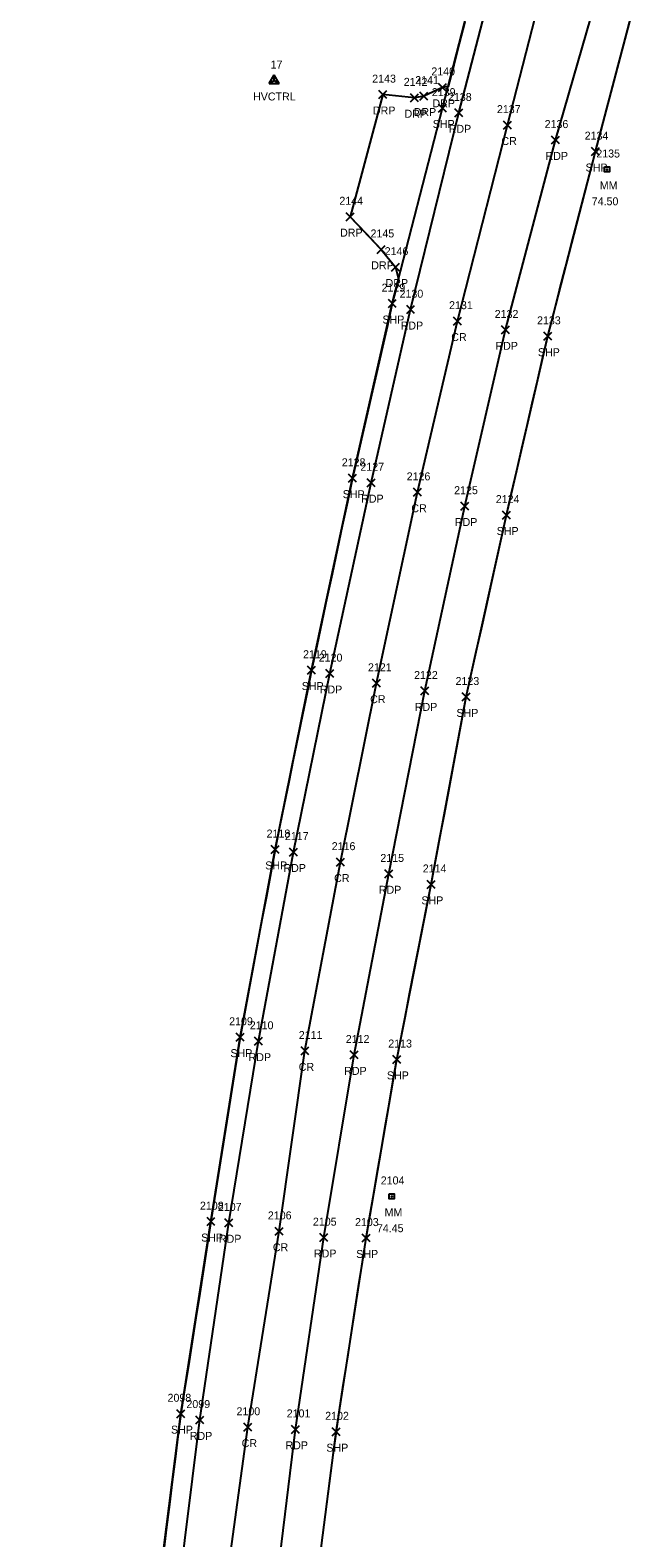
# Model space of a CAD drawing. Extents: x 1688195 to 1692013, y 424605 to 441234.
# Drawn here: x 1690667.5 to 1690820.9, y 437534.4 to 437913 of the extents above; entities that cross this region are included whole.
import ezdxf

# ---------------------------------------------------------------- set-up
doc = ezdxf.new("R2010")
doc.units = 0
for name, color, linetype in [('C_A', 7, 'Continuous'), ('C_I', 7, 'Continuous'), ('CPSM', 7, 'Continuous'), ('LSOGP', 7, 'Continuous'), ('P_A', 7, 'Continuous'), ('P_I', 7, 'Continuous'), ('P_TIC', 7, 'Continuous'), ('PET', 7, 'Continuous'), ('PRC', 7, 'Continuous'), ('PSP', 7, 'Continuous'), ('R_A', 7, 'Continuous'), ('R_I', 7, 'Continuous'), ('R_TIC', 7, 'Continuous'), ('RDP', 7, 'Continuous'), ('S_A', 7, 'Continuous'), ('S_C', 7, 'Continuous'), ('S_I', 7, 'Continuous'), ('SRM', 7, 'Continuous')]:
    doc.layers.add(name, color=color, linetype=linetype)

msp = doc.modelspace()

# ---------------------------------------------------------------- linework, layer by layer
at = {"layer": 'CPSM'}
for p, q in [((1690727.56, 437899.59), (1690728.81, 437901.75)), ((1690727.56, 437899.59), (1690728.81, 437900.31)), ((1690730.06, 437899.59), (1690728.81, 437901.75)), ((1690728.81, 437900.31), (1690728.81, 437901.75)), ((1690728.81, 437900.31), (1690728.81, 437900.31)), ((1690728.81, 437900.31), (1690730.06, 437899.59)), ((1690727.56, 437899.59), (1690730.06, 437899.59))]:
    msp.add_line(p, q, dxfattribs=at)
at = {"layer": 'LSOGP'}
for points in [[(1690776.67, 437915.01), (1690775.27, 437909.61), (1690773.88, 437904.21), (1690772.49, 437898.8), (1690771.05, 437898.6), (1690766.36, 437896.42), (1690764.05, 437895.98), (1690756.12, 437896.79), (1690747.87, 437866.12), (1690751.79, 437862.02), (1690755.7, 437857.92), (1690759.31, 437853.47), (1690760.06, 437850.44), (1690758.48, 437844.3), (1690757.23, 437838.82), (1690755.98, 437833.34), (1690754.73, 437827.86), (1690753.48, 437822.38), (1690752.23, 437816.9), (1690750.99, 437811.42), (1690749.74, 437805.94), (1690748.49, 437800.46), (1690747.2, 437794.44), (1690745.92, 437788.42), (1690744.63, 437782.39), (1690743.35, 437776.37), (1690742.06, 437770.35), (1690740.77, 437764.33), (1690739.49, 437758.3), (1690738.2, 437752.28), (1690737.06, 437746.65), (1690735.91, 437741.02), (1690734.76, 437735.4), (1690733.62, 437729.77), (1690732.47, 437724.14), (1690731.33, 437718.51), (1690730.18, 437712.88), (1690729.03, 437707.25), (1690727.94, 437701.36), (1690726.85, 437695.47), (1690725.75, 437689.58), (1690724.66, 437683.69), (1690723.57, 437677.79), (1690722.48, 437671.9), (1690721.38, 437666.01), (1690720.29, 437660.12), (1690719.37, 437654.33), (1690718.46, 437648.54), (1690717.54, 437642.75), (1690716.62, 437636.97), (1690715.7, 437631.18), (1690714.78, 437625.39), (1690713.87, 437619.61), (1690712.95, 437613.82), (1690712, 437607.79), (1690711.06, 437601.76), (1690710.11, 437595.73), (1690709.16, 437589.7), (1690708.21, 437583.67), (1690707.27, 437577.64), (1690706.32, 437571.61), (1690705.37, 437565.59), (1690704.66, 437559.89), (1690703.94, 437554.19), (1690703.22, 437548.49), (1690702.51, 437542.8), (1690701.79, 437537.1), (1690701.08, 437531.4)], [(1690740.64, 437531.86), (1690741.39, 437537.7), (1690742.14, 437543.54), (1690742.89, 437549.38), (1690743.64, 437555.22), (1690745.33, 437567.14), (1690746.26, 437573.22), (1690747.2, 437579.3), (1690748.14, 437585.38), (1690749.07, 437591.46), (1690750.01, 437597.54), (1690750.95, 437603.62), (1690751.89, 437609.7), (1690752.85, 437615.3), (1690753.81, 437620.91), (1690754.77, 437626.51), (1690755.73, 437632.11), (1690756.7, 437637.72), (1690757.66, 437643.32), (1690758.62, 437648.93), (1690759.58, 437654.53), (1690760.66, 437660.02), (1690761.75, 437665.52), (1690762.83, 437671.01), (1690763.91, 437676.5), (1690765, 437682), (1690766.08, 437687.49), (1690767.16, 437692.98), (1690768.24, 437698.48), (1690769.34, 437704.36), (1690770.44, 437710.24), (1690771.54, 437716.13), (1690772.65, 437722.01), (1690773.75, 437727.89), (1690774.85, 437733.78), (1690775.95, 437739.66), (1690777.05, 437745.54), (1690778.31, 437751.25), (1690779.57, 437756.96), (1690780.83, 437762.67), (1690782.1, 437768.38), (1690783.36, 437774.09), (1690784.62, 437779.8), (1690785.88, 437785.51), (1690787.15, 437791.22), (1690788.44, 437796.83), (1690789.73, 437802.44), (1690791.03, 437808.05), (1690792.32, 437813.66), (1690793.62, 437819.27), (1690794.91, 437824.88), (1690796.21, 437830.49), (1690797.5, 437836.1), (1690798.99, 437841.9), (1690800.49, 437847.69), (1690801.98, 437853.49), (1690803.48, 437859.29), (1690804.98, 437865.08), (1690806.47, 437870.88), (1690807.97, 437876.67), (1690809.46, 437882.47), (1690810.89, 437887.87), (1690812.31, 437893.26), (1690813.74, 437898.66), (1690815.17, 437904.06), (1690816.59, 437909.45), (1690818.02, 437914.85)]]:
    msp.add_lwpolyline(points, dxfattribs=at)
at = {"layer": 'P_TIC'}
for points in [[(1690770.1, 437892.4), (1690772.1, 437894.4)], [(1690772.1, 437892.4), (1690770.1, 437894.4)], [(1690774.14, 437891.19), (1690776.14, 437893.19)], [(1690776.14, 437891.19), (1690774.14, 437893.19)], [(1690786.43, 437888.13), (1690788.43, 437890.13)], [(1690788.43, 437888.13), (1690786.43, 437890.13)], [(1690798.47, 437884.38), (1690800.47, 437886.38)], [(1690800.47, 437884.38), (1690798.47, 437886.38)], [(1690808.46, 437881.47), (1690810.46, 437883.47)], [(1690810.46, 437881.47), (1690808.46, 437883.47)], [(1690757.48, 437843.3), (1690759.48, 437845.3)], [(1690759.48, 437843.3), (1690757.48, 437845.3)], [(1690762.08, 437841.79), (1690764.08, 437843.79)], [(1690764.08, 437841.79), (1690762.08, 437843.79)], [(1690773.84, 437838.91), (1690775.84, 437840.91)], [(1690775.84, 437838.91), (1690773.84, 437840.91)], [(1690785.88, 437836.7), (1690787.88, 437838.7)], [(1690787.88, 437836.7), (1690785.88, 437838.7)], [(1690796.5, 437835.1), (1690798.5, 437837.1)], [(1690798.5, 437835.1), (1690796.5, 437837.1)], [(1690747.49, 437799.46), (1690749.49, 437801.46)], [(1690749.49, 437799.46), (1690747.49, 437801.46)], [(1690752.16, 437798.33), (1690754.16, 437800.33)], [(1690754.16, 437798.33), (1690752.16, 437800.33)], [(1690763.83, 437795.93), (1690765.83, 437797.93)], [(1690765.83, 437795.93), (1690763.83, 437797.93)], [(1690775.69, 437792.46), (1690777.69, 437794.46)], [(1690777.69, 437792.46), (1690775.69, 437794.46)], [(1690786.15, 437790.22), (1690788.15, 437792.22)], [(1690788.15, 437790.22), (1690786.15, 437792.22)], [(1690737.2, 437751.28), (1690739.2, 437753.28)], [(1690739.2, 437751.28), (1690737.2, 437753.28)], [(1690741.78, 437750.42), (1690743.78, 437752.42)], [(1690743.78, 437750.42), (1690741.78, 437752.42)], [(1690753.49, 437747.99), (1690755.49, 437749.99)], [(1690755.49, 437747.99), (1690753.49, 437749.99)], [(1690765.63, 437746.05), (1690767.63, 437748.05)], [(1690767.63, 437746.05), (1690765.63, 437748.05)], [(1690776.05, 437744.54), (1690778.05, 437746.54)], [(1690778.05, 437744.54), (1690776.05, 437746.54)], [(1690728.03, 437706.25), (1690730.03, 437708.25)], [(1690730.03, 437706.25), (1690728.03, 437708.25)], [(1690732.64, 437705.61), (1690734.64, 437707.61)], [(1690734.64, 437705.61), (1690732.64, 437707.61)], [(1690744.44, 437703.08), (1690746.44, 437705.08)], [(1690746.44, 437703.08), (1690744.44, 437705.08)], [(1690756.6, 437700.13), (1690758.6, 437702.13)], [(1690758.6, 437700.13), (1690756.6, 437702.13)], [(1690767.24, 437697.48), (1690769.24, 437699.48)], [(1690769.24, 437697.48), (1690767.24, 437699.48)], [(1690719.29, 437659.12), (1690721.29, 437661.12)], [(1690721.29, 437659.12), (1690719.29, 437661.12)], [(1690723.9, 437658.11), (1690725.9, 437660.11)], [(1690725.9, 437658.11), (1690723.9, 437660.11)], [(1690735.55, 437655.66), (1690737.55, 437657.66)], [(1690737.55, 437655.66), (1690735.55, 437657.66)], [(1690747.91, 437654.66), (1690749.91, 437656.66)], [(1690749.91, 437654.66), (1690747.91, 437656.66)], [(1690758.58, 437653.53), (1690760.58, 437655.53)], [(1690760.58, 437653.53), (1690758.58, 437655.53)], [(1690711.95, 437612.82), (1690713.95, 437614.82)], [(1690713.95, 437612.82), (1690711.95, 437614.82)], [(1690716.45, 437612.51), (1690718.45, 437614.51)], [(1690718.45, 437612.51), (1690716.45, 437614.51)], [(1690729.06, 437610.38), (1690731.06, 437612.38)], [(1690731.06, 437610.38), (1690729.06, 437612.38)], [(1690740.31, 437608.81), (1690742.31, 437610.81)], [(1690742.31, 437608.81), (1690740.31, 437610.81)], [(1690750.89, 437608.7), (1690752.89, 437610.7)], [(1690752.89, 437608.7), (1690750.89, 437610.7)], [(1690704.37, 437564.59), (1690706.37, 437566.59)], [(1690706.37, 437564.59), (1690704.37, 437566.59)], [(1690709.13, 437563.01), (1690711.13, 437565.01)], [(1690711.13, 437563.01), (1690709.13, 437565.01)], [(1690721.22, 437561.2), (1690723.22, 437563.2)], [(1690723.22, 437561.2), (1690721.22, 437563.2)], [(1690733.16, 437560.66), (1690735.16, 437562.66)], [(1690735.16, 437560.66), (1690733.16, 437562.66)], [(1690743.39, 437560.06), (1690745.39, 437562.06)], [(1690745.39, 437560.06), (1690743.39, 437562.06)]]:
    msp.add_lwpolyline(points, dxfattribs=at)
at = {"layer": 'PET'}
for points in [[(1690672.22, 437133.51), (1690675.32, 437180.59), (1690679.01, 437229.3), (1690682.55, 437279.56), (1690686.24, 437327.7), (1690690.1, 437375.18), (1690694.44, 437424.13), (1690699.57, 437468.9), (1690704.53, 437518.9), (1690710.13, 437564.01), (1690717.45, 437613.51), (1690724.9, 437659.11), (1690733.64, 437706.61), (1690742.78, 437751.42), (1690753.16, 437799.33), (1690763.08, 437842.79), (1690775.14, 437892.19), (1690786.57, 437936.04)], [(1690696.48, 437132.39), (1690699.66, 437177.7), (1690703.13, 437226.98), (1690706.92, 437277.15), (1690710.83, 437325.78), (1690714.61, 437373.28), (1690718.51, 437419.73), (1690723.31, 437467.32), (1690728.46, 437514.97), (1690734.16, 437561.66), (1690741.31, 437609.81), (1690748.91, 437655.66), (1690757.6, 437701.13), (1690766.63, 437747.05), (1690776.69, 437793.46), (1690786.88, 437837.7), (1690799.47, 437885.38), (1690811.72, 437928.04)]]:
    msp.add_lwpolyline(points, dxfattribs=at)
at = {"layer": 'PRC'}
msp.add_lwpolyline([(1690683.84, 437132.47), (1690687.9, 437179.25), (1690690.8, 437228.34), (1690694.3, 437277.81), (1690698.39, 437326.64), (1690702.07, 437373.44), (1690706.22, 437422.68), (1690711.1, 437467.75), (1690716.15, 437518.28), (1690722.22, 437562.2), (1690730.06, 437611.38), (1690736.55, 437656.66), (1690745.44, 437704.08), (1690754.49, 437748.99), (1690764.83, 437796.93), (1690774.84, 437839.91), (1690787.43, 437889.13), (1690798.27, 437931.55)], dxfattribs=at)
at = {"layer": 'PSP'}
for points in [[(1690667.55, 437134.28), (1690670.88, 437180.54), (1690674.46, 437230.34), (1690677.75, 437279.66), (1690681.7, 437328.8), (1690685.23, 437375.51), (1690689.67, 437424.54), (1690694.03, 437469.91), (1690699.64, 437520.01), (1690705.37, 437565.59), (1690712.95, 437613.82), (1690720.29, 437660.12), (1690729.03, 437707.25), (1690738.2, 437752.28), (1690748.49, 437800.46), (1690758.48, 437844.3), (1690771.1, 437893.4), (1690782.23, 437936.63)], [(1690706.73, 437130.77), (1690709.86, 437177.48), (1690712.96, 437225.68), (1690716.45, 437277.35), (1690719.82, 437326.32), (1690723.69, 437372.72), (1690727.97, 437418.98), (1690733.02, 437466.84), (1690738.38, 437514.35), (1690744.39, 437561.06), (1690751.89, 437609.7), (1690759.58, 437654.53), (1690768.24, 437698.48), (1690777.05, 437745.54), (1690787.15, 437791.22), (1690797.5, 437836.1), (1690809.46, 437882.47), (1690820.87, 437925.64)]]:
    msp.add_lwpolyline(points, dxfattribs=at)
at = {"layer": 'R_TIC'}
for points in [[(1690755.12, 437895.79), (1690757.12, 437897.79)], [(1690757.12, 437895.79), (1690755.12, 437897.79)], [(1690763.05, 437894.98), (1690765.05, 437896.98)], [(1690765.05, 437894.98), (1690763.05, 437896.98)], [(1690765.36, 437895.42), (1690767.36, 437897.42)], [(1690767.36, 437895.42), (1690765.36, 437897.42)], [(1690770.05, 437897.6), (1690772.05, 437899.6)], [(1690772.05, 437897.6), (1690770.05, 437899.6)], [(1690746.87, 437865.12), (1690748.87, 437867.12)], [(1690748.87, 437865.12), (1690746.87, 437867.12)], [(1690754.7, 437856.92), (1690756.7, 437858.92)], [(1690756.7, 437856.92), (1690754.7, 437858.92)], [(1690758.31, 437852.47), (1690760.31, 437854.47)], [(1690760.31, 437852.47), (1690758.31, 437854.47)]]:
    msp.add_lwpolyline(points, dxfattribs=at)
at = {"layer": 'RDP'}
for points in [[(1690771.05, 437898.6), (1690766.36, 437896.42), (1690764.05, 437895.98), (1690756.12, 437896.79)], [(1690747.87, 437866.12), (1690755.7, 437857.92), (1690759.31, 437853.47)]]:
    msp.add_lwpolyline(points, dxfattribs=at)
at = {"layer": 'SRM'}
for points in [[(1690811.75, 437878.61), (1690813, 437878.61), (1690813, 437877.36), (1690811.75, 437877.36)], [(1690757.72, 437620.78), (1690758.97, 437620.78), (1690758.97, 437619.53), (1690757.72, 437619.53)]]:
    msp.add_lwpolyline(points, close=True, dxfattribs=at)
for centre in [(1690812.38, 437877.99), (1690758.35, 437620.16)]:
    msp.add_circle(centre, 0.0833, dxfattribs=at)

# ---------------------------------------------------------------- texts
at = {"layer": 'C_A'}
msp.add_text('HVCTRL', height=2, dxfattribs=at).set_placement((1690723.51, 437895.31))
at = {"layer": 'C_I'}
msp.add_text('17', height=2, dxfattribs=at).set_placement((1690727.91, 437903.31))
at = {"layer": 'P_A'}
for s, p in [('SHP', (1690768.63, 437888.4)), ('RDP', (1690772.63, 437887.19)), ('CR', (1690785.87, 437884.13)), ('RDP', (1690796.95, 437880.38)), ('SHP', (1690807, 437877.47)), ('SHP', (1690756.01, 437839.3)), ('RDP', (1690760.57, 437837.79)), ('CR', (1690773.28, 437834.91)), ('RDP', (1690784.36, 437832.7)), ('SHP', (1690795.03, 437831.1)), ('SHP', (1690746.02, 437795.46)), ('RDP', (1690750.65, 437794.33)), ('CR', (1690763.26, 437791.93)), ('RDP', (1690774.18, 437788.46)), ('SHP', (1690784.68, 437786.22)), ('SHP', (1690735.74, 437747.28)), ('RDP', (1690740.26, 437746.42)), ('CR', (1690752.92, 437743.99)), ('RDP', (1690764.12, 437742.05)), ('SHP', (1690774.58, 437740.54)), ('SHP', (1690726.57, 437702.25)), ('RDP', (1690731.13, 437701.61)), ('CR', (1690743.87, 437699.08)), ('RDP', (1690755.09, 437696.13)), ('SHP', (1690765.78, 437693.48)), ('SHP', (1690717.83, 437655.12)), ('RDP', (1690722.39, 437654.11)), ('CR', (1690734.98, 437651.66)), ('RDP', (1690746.4, 437650.66)), ('SHP', (1690757.12, 437649.53)), ('SHP', (1690710.48, 437608.82)), ('RDP', (1690714.94, 437608.51)), ('CR', (1690728.49, 437606.38)), ('RDP', (1690738.8, 437604.81)), ('SHP', (1690749.42, 437604.7)), ('SHP', (1690702.91, 437560.59)), ('RDP', (1690707.62, 437559.01)), ('CR', (1690720.65, 437557.2)), ('RDP', (1690731.65, 437556.66)), ('SHP', (1690741.92, 437556.06))]:
    msp.add_text(s, height=2, dxfattribs=at).set_placement(p)
at = {"layer": 'P_I'}
for s, p in [('2139', (1690768.4, 437896.4)), ('2138', (1690772.45, 437895.19)), ('2137', (1690784.74, 437892.13)), ('2136', (1690796.72, 437888.38)), ('2134', (1690806.77, 437885.47)), ('2129', (1690755.78, 437847.3)), ('2130', (1690760.3, 437845.79)), ('2131', (1690772.72, 437842.91)), ('2132', (1690784.18, 437840.7)), ('2133', (1690794.81, 437839.1)), ('2128', (1690745.79, 437803.46)), ('2127', (1690750.47, 437802.33)), ('2126', (1690762.08, 437799.93)), ('2125', (1690774, 437796.46)), ('2124', (1690784.45, 437794.22)), ('2119', (1690736.07, 437755.28)), ('2120', (1690740, 437754.42)), ('2121', (1690752.36, 437751.99)), ('2122', (1690763.94, 437750.05)), ('2123', (1690774.35, 437748.54)), ('2118', (1690726.91, 437710.25)), ('2117', (1690731.51, 437709.61)), ('2116', (1690743.26, 437707.08)), ('2115', (1690755.47, 437704.13)), ('2114', (1690766.12, 437701.48)), ('2109', (1690717.51, 437663.12)), ('2110', (1690722.69, 437662.11)), ('2111', (1690734.99, 437659.66)), ('2112', (1690746.79, 437658.66)), ('2113', (1690757.46, 437657.53)), ('2108', (1690710.18, 437616.82)), ('2107', (1690714.68, 437616.51)), ('2106', (1690727.23, 437614.38)), ('2105', (1690738.54, 437612.81)), ('2103', (1690749.11, 437612.7)), ('2098', (1690702.04, 437568.59)), ('2099', (1690706.78, 437567.01)), ('2100', (1690719.36, 437565.2)), ('2101', (1690731.96, 437564.66)), ('2102', (1690741.62, 437564.06))]:
    msp.add_text(s, height=2, dxfattribs=at).set_placement(p)
at = {"layer": 'R_A'}
for p in [(1690753.61, 437891.79), (1690761.54, 437890.98), (1690763.84, 437891.42), (1690768.54, 437893.6), (1690745.36, 437861.12), (1690753.19, 437852.92), (1690756.79, 437848.47)]:
    msp.add_text('DRP', height=2, dxfattribs=at).set_placement(p)
at = {"layer": 'R_I'}
for s, p in [('2140', (1690768.27, 437901.6)), ('2143', (1690753.43, 437899.79)), ('2142', (1690761.35, 437898.98)), ('2141', (1690764.23, 437899.42)), ('2144', (1690745.18, 437869.12)), ('2145', (1690753.01, 437860.92)), ('2146', (1690756.56, 437856.47))]:
    msp.add_text(s, height=2, dxfattribs=at).set_placement(p)
at = {"layer": 'S_A'}
for p in [(1690810.57, 437872.99), (1690756.53, 437615.16)]:
    msp.add_text('MM', height=2, dxfattribs=at).set_placement(p)
at = {"layer": 'S_C'}
for s, p in [('74.50', (1690808.54, 437868.99)), ('74.45', (1690754.6, 437611.16))]:
    msp.add_text(s, height=2, dxfattribs=at).set_placement(p)
at = {"layer": 'S_I'}
for s, p in [('2135', (1690809.69, 437880.99)), ('2104', (1690755.57, 437623.16))]:
    msp.add_text(s, height=2, dxfattribs=at).set_placement(p)

doc.saveas('drawing.dxf')
